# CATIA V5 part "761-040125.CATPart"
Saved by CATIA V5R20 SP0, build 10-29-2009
Part number: 761-040125
Source: Unknown
Property "ARTICLENO": "761-040125"
Property "BOMINFO": "761-040125"
Property "CODE": "761-040125"
Property "H": "40.000"
Property "L1": "125.000"
Property "L2": "100.000"
Property "LINA": "761-040125"
Property "NB": "761-040125"
Property "NBSYN": "$CODE."
Property "NN": "761"
Property "NT": "VW/AUDI Keys"
Property "P": "4.000"
Property "SUPPLIER": "CF"
Bounding box of the stored display mesh (mm): x -62.5 to 62.5, y 0 to 40, z -11 to 11
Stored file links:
  C:\Users\Utente\Desktop\3D files 761\761-040125.CATPart
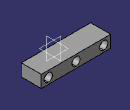
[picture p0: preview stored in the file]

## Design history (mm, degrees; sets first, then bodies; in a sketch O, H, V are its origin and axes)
Body1 "Geometry.1" (main body)
  Solid1 "761-040125.catpart": solid without history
